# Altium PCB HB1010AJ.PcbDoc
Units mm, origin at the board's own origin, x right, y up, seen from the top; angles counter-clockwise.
Board outline 79 x 52 mm, 2 copper layers (Top Layer, Bottom Layer); 42 components, 44 nets, 138 pads, 30 vias.
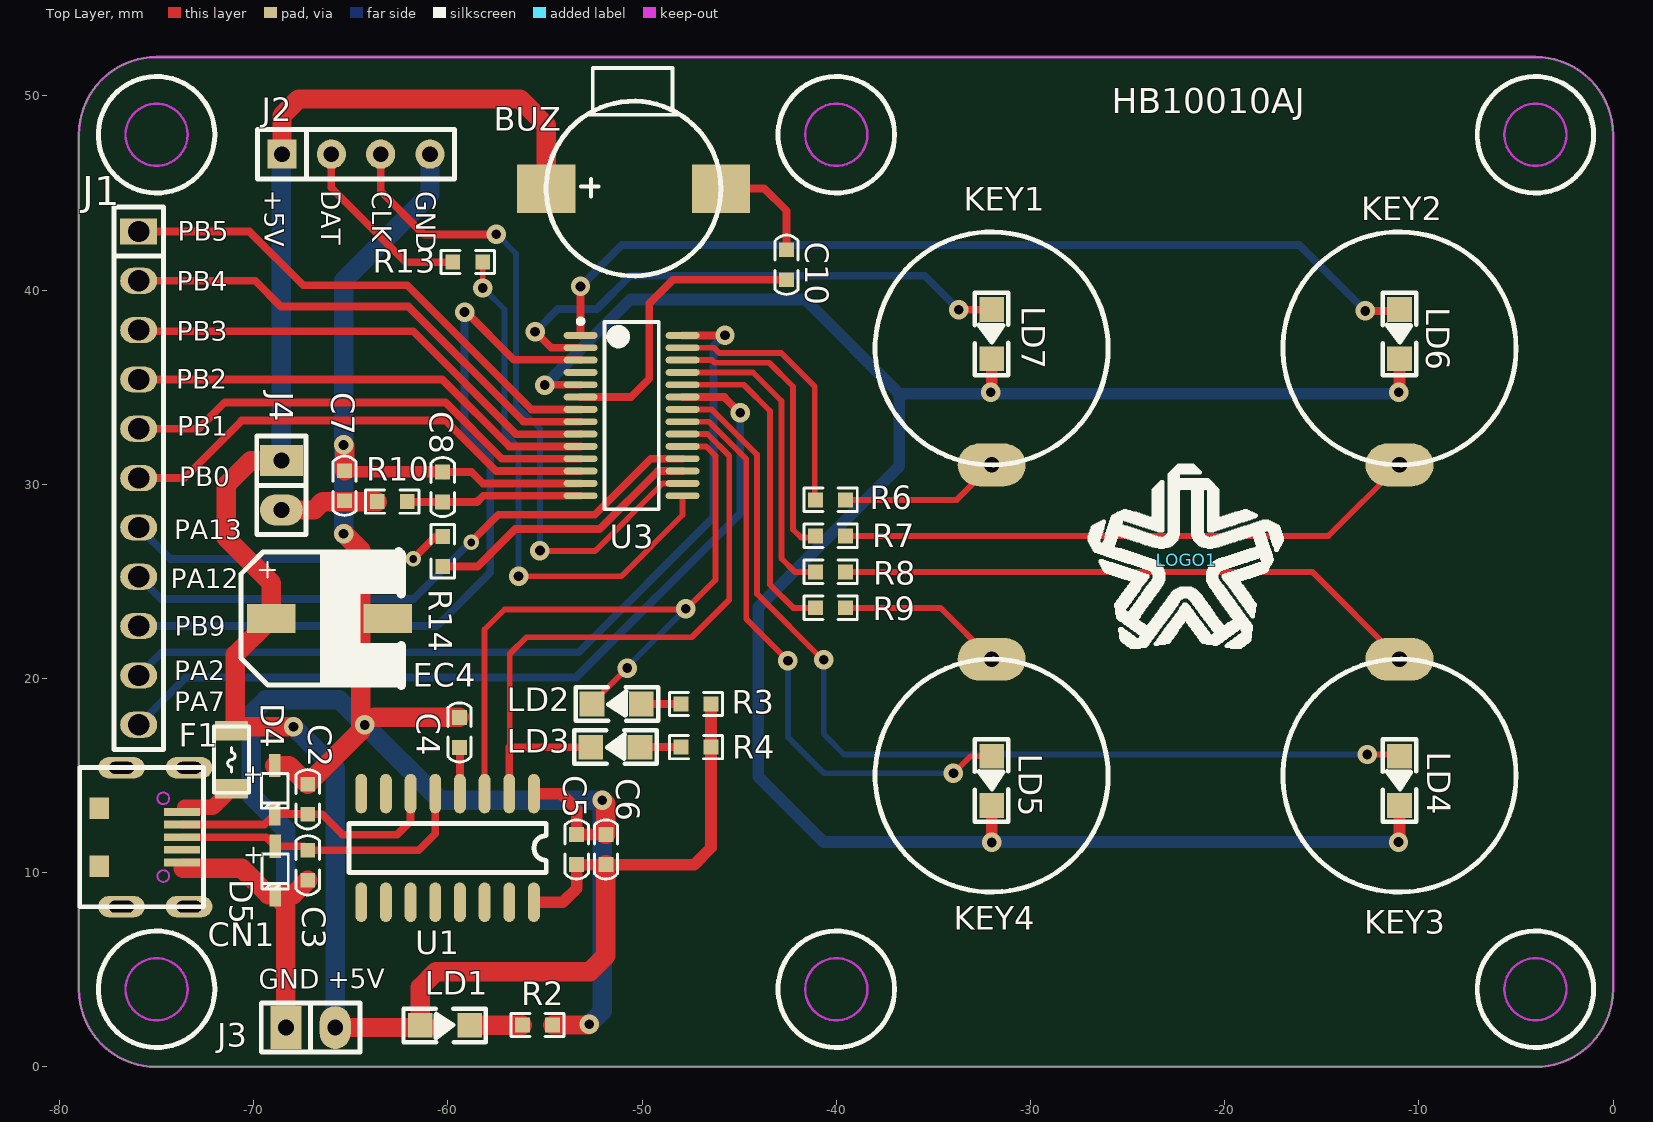
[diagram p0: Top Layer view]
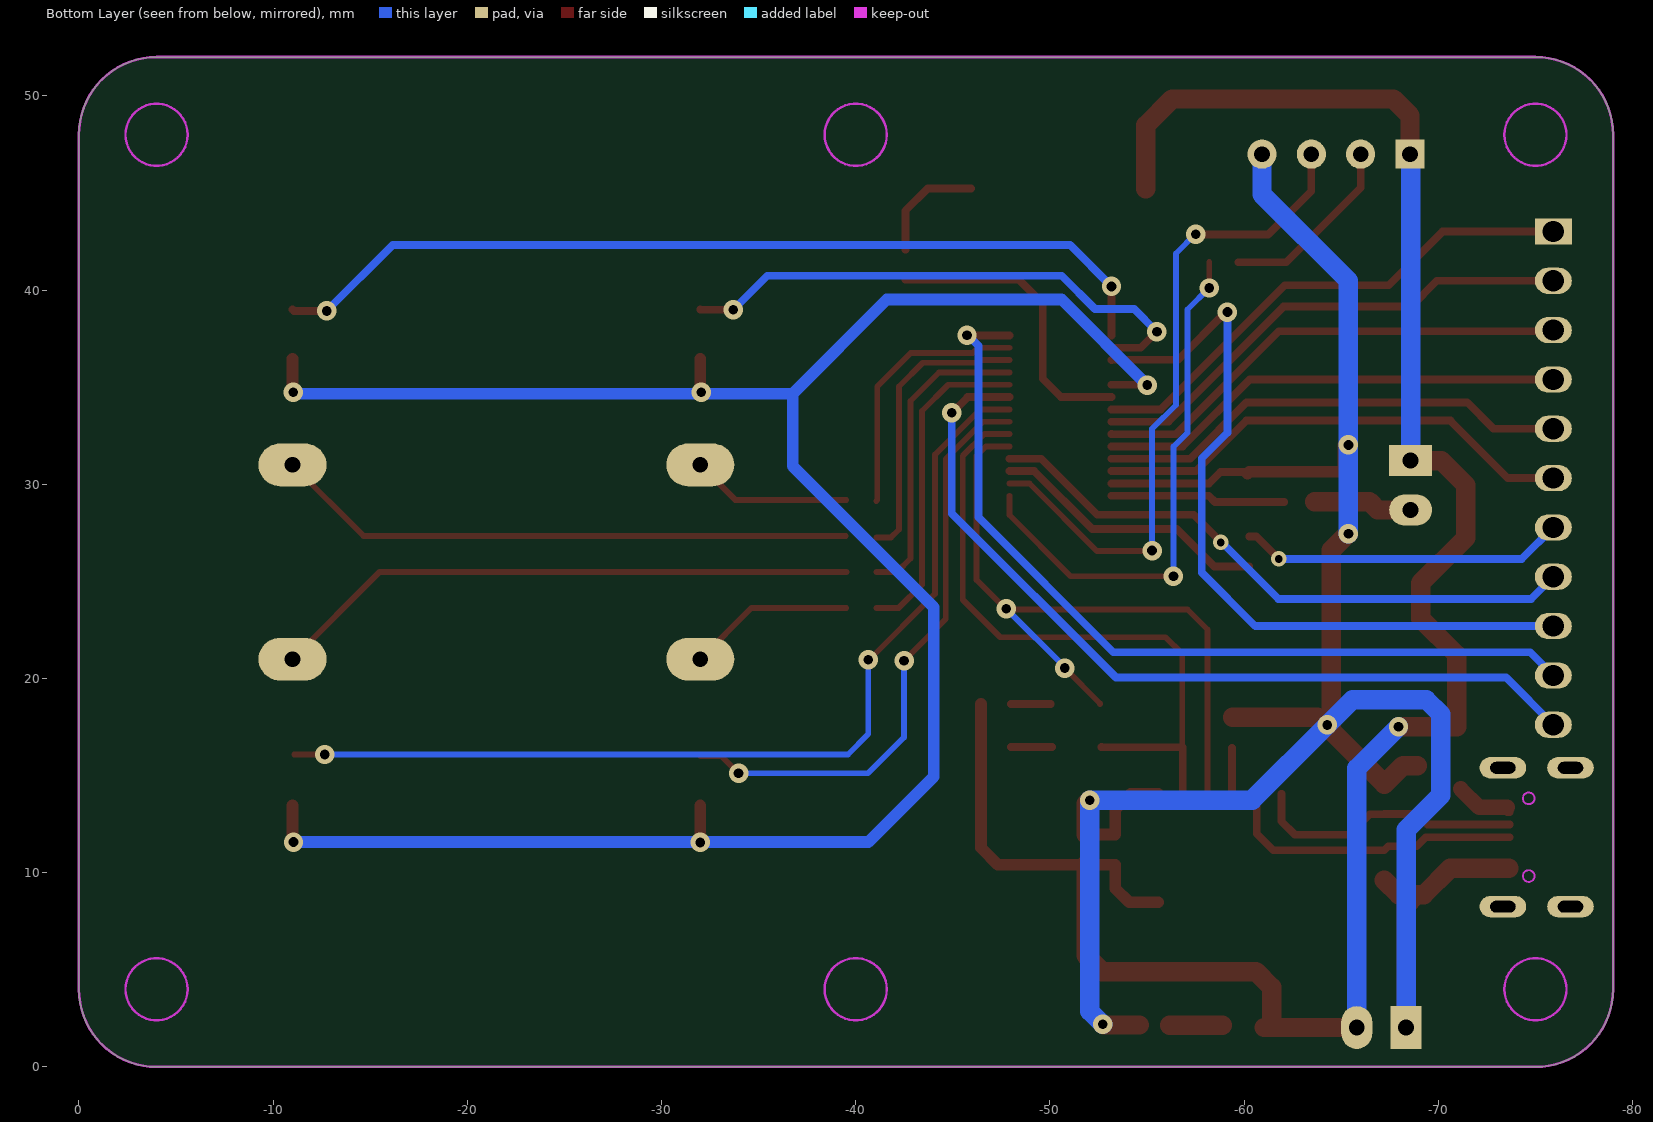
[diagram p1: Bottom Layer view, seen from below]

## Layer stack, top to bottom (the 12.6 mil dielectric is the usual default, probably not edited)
Top Layer: signal copper 0.0356
Dielectric: dielectric 0.32, FR-4, Dk 4.8
Bottom Layer: signal copper 0.0356

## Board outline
-79,4 -79,48 cw(c-75,48) -75,52 -4,52 cw(c-4,48) 0,48 0,4 cw(c-4,4) -4,0 -75,0 cw(c-75,4)

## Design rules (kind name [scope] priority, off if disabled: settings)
Clearance 板边 [All] p1 off: gap=0.6
Clearance [All] p2: gap=0.2
ComponentClearance [All] p1 off: gap=0.254 collisioncheckmode=3 verticalgap=0.254 showdistances=FALSE
MinimumSolderMaskSliver [All] p1: minsoldermaskwidth=0
PlaneClearance [All] p1: clearance=0.6
PlaneConnect [All] p1: planeconnectstyle=Relief reliefexpansion=0.508 reliefentries=4 reliefconductorwidth=0.254 reliefairgap=0
PolygonConnect PolygonConnect_1 [IsVia] p1: connectstyle=Direct reliefconductorwidth=0.254 reliefentries=4 polygonreliefangle="90 Angle"
PolygonConnect [All] p2: connectstyle=Relief reliefconductorwidth=0.3 reliefentries=4 polygonreliefangle="90 Angle"
RoutingVias [All] p1: holewidth=0.5 width=1 viastyle="Through Hole" minholewidth=0.4 minwidth=0.8 maxholewidth=0.6 maxwidth=1.2
SilkToSilkClearance [All] p1: silktosilkclearance=0
SilkscreenOverComponentPads SilkToSolderMaskClearance [IsPad] p1: minsilkscreentomaskgap=0
SolderMaskExpansion [All] p1: expansion=0.102
TestPointUsage FabricationTestPointUsage [All] p1: valid=0 allowmultiple=FALSE
Testpoint FabricationTestpoint [All] p1: side=3 testpointundercomponent=TRUE minsize=1.016 maxsize=2.54 preferedsize=1.524 minholesize=0 maxholesize=1.016 preferedholesize=0.813 testpointgrid=0.025 style=297 order=0-112345678
Width [All] p1: maxlimit=1 minlimit=0.3 preferedwidth=0.3
18 further rules are at their usual default settings.

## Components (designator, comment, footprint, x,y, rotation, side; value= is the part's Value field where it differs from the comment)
BUZ "BUZZ" BUZZ-90X32-SMD -50.44,45.23 r0 top
C2 "DNP/100pF/50V" 0603C -67.22,14.56 r270 top
C3 "DNP/100pF/50V" 0603C -67.22,11.16 r270 top
C4 "0.1uF/25V" 0603C -59.4,18 r270 top
C5 "10uF/25V" 0603C -53.37,11.97 r270 top
C6 "0.1uF/25V" 0603C -51.86,11.97 r270 top
C7 "10uF/25V" 0603C -65.32,29.15 r90 top
C8 "0.1uF/25V" 0603C -60.27,29.09 r90 top
C10 "0603-25V-2.2μF±10% X5R" 0603c -42.56,40.53 r90 top
CN1 "USB micro 5P" "MicroUSB - 7P2" -73.68,11.83 r270 top
D4 "DNP/PESD3V3L1BA" SOD-323 -68.9,15.62 r270 top
D5 "DNP/PESD3V3L1BA" SOD-323 -68.88,11.47 r270 top
EC4 "220uF±20% 10V SMD,6.3x5.4mm" ECAP-D6.3 -66.09,23.09 r0 top
F1 "6V 500mA" SF1206 -71.15,15.82 r90 top
J1 "CON11" sip11 -75.92,43.02 r270 top
J2 "CON4" SIP4 -68.54,47 r0 top
J3 "" sip2 -68.34,2.03 r0 top
J4 "" SIP2 -68.57,31.22 r270 top
KEY1 "" 弹簧6MM -32,37 r0 top locked
KEY2 "" 弹簧6MM -11,37 r0 top locked
KEY3 "" 弹簧6MM -11,15 r180 top locked
KEY4 "" 弹簧6MM -32,15 r180 top locked
LD1 "17-21SURC/S530-A3/TR8  发光二极管/0805 红灯 (Iv=61mcd(Typ) @IF=20mA)" D0805 -61.42,2.14 r0 top
LD2 "DNP" D0805 -50.04,18.69 r180 top
LD3 "DNP" D0805 -50.11,16.47 r180 top
LD4 "17-21SURC/S530-A3/TR8  发光二极管/0805 红灯 (Iv=61mcd(Typ) @IF=20mA)" D0805 -11,16 r270 top
LD5 "17-21SURC/S530-A3/TR8  发光二极管/0805 红灯 (Iv=61mcd(Typ) @IF=20mA)" D0805 -32,16 r270 top
LD6 "17-21SURC/S530-A3/TR8  发光二极管/0805 红灯 (Iv=61mcd(Typ) @IF=20mA)" D0805 -11,39 r270 top
LD7 "17-21SURC/S530-A3/TR8  发光二极管/0805 红灯 (Iv=61mcd(Typ) @IF=20mA)" D0805 -32,39 r270 top
LOGO1 "LOGO" LOGO_HED_10mm -21.96,26.1 r0 top
R2 "1K" 0603 -56.16,2.16 r0 top
R3 "DNP" 0603 -46.45,18.69 r180 top
R4 "DNP" 0603 -46.45,16.47 r180 top
R6 "10KΩ(1002) ±1% 0603WAF1002T5E" 0603 -39.52,29.2 r180 top
R7 "10KΩ(1002) ±1% 0603WAF1002T5E" 0603 -39.52,27.347 r180 top
R8 "10KΩ(1002) ±1% 0603WAF1002T5E" 0603 -39.52,25.493 r180 top
R9 "10KΩ(1002) ±1% 0603WAF1002T5E" 0603 -39.52,23.64 r180 top
R10 "0603WAF0000T5E 0R 1% 0603" R0603 -63.64,29.11 r0 top
R13 "0603WAF0000T5E 0R 1% 0603" R0603 -59.75,41.45 r0 top
R14 "0603WAF0000T5E 0R 1% 0603" R0603 -60.26,27.32 r270 top
U1 "CH340C  SOP-16_150mil" SO-16 -55.57,14.07 r270 top
U3 "CIU32F011I3FBxJ" SSOP28 -50.54,33.54 r0 top

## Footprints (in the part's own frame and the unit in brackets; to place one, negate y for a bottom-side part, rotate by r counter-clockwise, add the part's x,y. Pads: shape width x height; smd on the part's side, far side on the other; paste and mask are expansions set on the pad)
0603 [mil]
  rect 30x30 smd: 1(0,0) 2(61.02,0)
  silkscreen extent -24,-24 85,24
0603C [mil]
  rect 30x30 smd: 1(0,0) 2(61.02,0)
  silkscreen extent -29,-24 90,24
0603c [mil]
  rect 30x30 smd: 1(0,0) 2(61.02,0)
  silkscreen extent -29,-24 90,24
BUZZ-90X32-SMD [mm]
  rect 3x2.5 smd: 1(-4.5,0) 2(4.5,0)
  silkscreen extent -4.5,-4.5 4.5,6.2
D0805 [mm]
  rect 1.27x1.27 smd: 1(0,0) 2(2.54,0)
  silkscreen extent -0.86,-0.86 3.38,0.86
ECAP-D6.3 [mm]
  rect 2.5x1.5 smd: 1(-3,-0.007) 2(3,-0.007)
  silkscreen extent -4.57,-3.43 3.68,3.43
LOGO_HED_10mm [mm]
  silkscreen extent -5,-4.47 4.9,4.88
"MicroUSB - 7P2" [mm] "MicroUSB"
  rect 0.4x1.85 smd: 1(-1.3,0) 2(-0.65,0) 3(0,0) 4(0.65,0) 5(1.3,0)
  oval 1.1x2.4 hole 0.6 slot 1.3 at 90 deg: 6(-3.575,0.355) 6(-3.575,-3.125) 6(3.575,0.355) 6(3.575,-3.125)
  rect 1.1x1 smd: 7(-1.5,-4.275) 7(1.5,-4.275)
  Keep-Out Layer circle w0.1: c-2,-0.975 r0.3
  Keep-Out Layer circle w0.1: c2,-0.975 r0.3
  silkscreen extent -3.58,-5.28 3.58,1.09
R0603 [mil]
  rect 30x30 smd: 1(0,0) 2(61.02,0)
  silkscreen extent -24,-24 85,24
SF1206 [mm]
  rrect10% 1x1.7 smd: 1(-1.5,0) 2(1.5,0)
  silkscreen extent -1.7,-0.9 1.7,0.9
sip2 [mm]
  rect 1.6x2.2 hole 0.813: 1(0,0)
  oval 1.6x2.2 hole 0.813: 2(2.54,0)
  silkscreen extent -1.27,-1.27 3.81,1.27
SIP2 [mm]
  rect 1.6x2.2 hole 0.813: 1(0,0)
  oval 1.6x2.2 hole 0.813: 2(2.54,0)
  silkscreen extent -1.27,-1.27 3.81,1.27
SIP4 [mm]
  rect 1.5x1.5 hole 0.813: 1(0,0)
  round 1.5 hole 0.813: 2(2.54,0) 3(5.08,0) 4(7.62,0)
  silkscreen extent -1.27,-1.27 8.89,1.27
sip11 [mil]
  rect 53x75 hole 43: 1(0,0)
  oval 53x75 hole 43: 2(100,0) 3(200,0) 4(300,0) 5(400,0) 6(500,0) 7(600,0) 8(700,0) 9(800,0) 10(900,0) 11(1000,0)
  silkscreen extent -50,-50 1050,50
SO-16 [mil]
  oval 80x24 smd: 1(0,0) 2(0,-50) 3(0,-100) 4(0,-150) 5(0,-200) 6(0,-250) 7(0,-300) 8(0,-350) 9(220,-350) 10(220,-300) 11(220,-250) 12(220,-200) 13(220,-150) 14(220,-100) 15(220,-50) 16(220,0)
  silkscreen extent 60,-375 160,25
SOD-323 [mm]
  rect 1.2x0.6 smd: 1(0.1,-0.007) 2(2.6,-0.007)
  silkscreen extent 0.5,-0.69 2.3,0.66
SSOP28 [mm]
  oval 1.75x0.35 smd: 1(-2.625,4.127) 2(-2.625,3.492) 3(-2.625,2.857) 4(-2.625,2.222) 5(-2.625,1.587) 6(-2.625,0.953) 7(-2.625,0.318) 8(-2.625,-0.318) 9(-2.625,-0.953) 10(-2.625,-1.587) 11(-2.625,-2.222) 12(-2.625,-2.857) 13(-2.625,-3.492) 14(-2.625,-4.127) 15(2.625,-4.127) 16(2.625,-3.492) 17(2.625,-2.857) 18(2.625,-2.222) 19(2.625,-1.587) 20(2.625,-0.953) 21(2.625,-0.318) 22(2.625,0.318) 23(2.625,0.953) 24(2.625,1.587) 25(2.625,2.222) 26(2.625,2.857) 27(2.625,3.492) 28(2.625,4.127)
  silkscreen extent -2.75,-4.83 1.4,4.98, body extent -1.95,-4.95 1.95,4.95, height 1.75
弹簧6MM [mm]
  oval 3.5x2.2 hole 0.8: 1(0,-6)
  silkscreen extent -6,-6 6,6

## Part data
C2 C3 C4 C5 C6 C10: library part "cap 0603", "贴片电容"
C7 C8: library part CAP
D4 D5: library part TVS
EC4: library part E_CAP01
F1: library part Fuse_SMD, "贴片保险丝"
J1 J2: "Connector"
J3: library part CON2, "Connector"
J4: library part CON2, "2.54mm 1*2P?公插针/2.54mm 1*2P 直 排针"
KEY1 KEY2 KEY3 KEY4: library part CHUMO-PAD
LD1 LD2 LD3 LD4 LD5 LD6 LD7: library part LED
R2 R3 R4: library part "res 0603", "贴片电阻"
R6 R7 R8 R9: library part RES1
R10 R13 R14: library part Res2, "Resistor"
U1: library part CH340C, "IC"

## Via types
v1: diameter 1, hole 0.5, Top Layer to Bottom Layer, tented both sides, 28 vias
v2: diameter 0.8, hole 0.4, Top Layer to Bottom Layer, tented both sides, 2 vias

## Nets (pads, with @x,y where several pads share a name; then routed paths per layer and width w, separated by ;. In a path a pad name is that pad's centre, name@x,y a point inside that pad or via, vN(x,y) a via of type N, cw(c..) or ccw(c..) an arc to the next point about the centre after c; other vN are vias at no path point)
+5V: BUZ.1 C5.2 C6.2 EC4.1 F1.2 J2.1 J3.2 J4.1 LD1.1 R3.1 R4.1 U1.16 | length 112.5
  Top Layer w0.6: U1.16 -54.078,8.482 -53.37,9.19 C5.2 C6.2 -47.32,10.42 -46.45,11.29 R3.1
  Top Layer w1: J4.1 -70.15,31.22 -71.41,29.96 -71.41,27.24 -69.09,24.92 EC4.1 -70.95,21.223 -70.95,17.52 v1(-67.95,17.52) ; J2.1 -68.54,48.99 -67.69,49.84 -56.29,49.84 -54.94,48.49 BUZ.1 ; J3.2 LD1.1@-61.03,2.03 ; LD1.1 -61.42,4.1 -60.61,4.91 -52.69,4.91 -51.86,5.74 C6.2
  Bottom Layer w1: J4.1 -68.57,46.97 J2.1 ; v1(-67.95,17.52) -65.8,15.37 J3.2
BUZ: C10.1 U3.6 | length 15.4
  Top Layer w0.4: U3.6 -50.578,34.492 -49.63,35.44 -49.63,39.31 -48.41,40.53 C10.1
CLK: J2.3 U3.16 | length 34.8
  Top Layer w0.3: v1@-55.24,26.56 -52.43,26.56 -48.95,30.04 -47.923,30.04 U3.16
  Top Layer w0.4: J2.3 -63.46,45.09 -61.23,42.86 v1@-57.51,42.86
  Bottom Layer w0.3: v1@-57.51,42.91 -56.49,41.89 -56.49,34.09 -55.26,32.86 v1(-55.26,26.59)
  other v1: -57.51,42.87
COM1: LD4.2 LD5.2 LD6.2 LD7.2 U3.5 | length 114.1
  Top Layer w0.4: v1@-55.037,35.127 U3.5
  Top Layer w0.6: v1(-32.04,34.74) -32,34.78 LD7.2 ; v1(-32,11.56) LD5.2 ; v1(-11.05,11.58) -11,11.63 LD4.2 ; v1(-11.04,34.74) -11,34.78 LD6.2
  Bottom Layer w0.6: v1(-55.01,35.11) -50.6,39.52 -41.6,39.52 -36.75,34.67 ; v1(-11.05,11.58) -40.65,11.58 -44.02,14.95 -44.02,23.67 -36.75,30.94 -36.75,34.67 ; v1(-11.04,34.74) -11.11,34.67 -36.75,34.67
D_N: C2.2 CN1.2 D4.2 U1.6 | length 14.1
  Top Layer w0.4: CN1.2 -69.447,12.48 D4.2 C2.2@-67.23,13.02 ; C2.2 -66.47,13.01 -65.42,11.96 -62.62,11.96 -61.92,12.66 U1.6
D_P: C3.1 CN1.3 D5.1 U1.5 | length 15.7
  Top Layer w0.4: CN1.3 -69.347,11.83 D5.1 -67.43,11.37 C3.1 -61.5,11.16 -60.65,12.01 U1.5
DAT: J2.2 R13.1 | length 9.6
  Top Layer w0.4: J2.2 -66,45.27 -62.16,41.43 R13.1@-59.71,41.43
GND: C2.1 C3.2 C4.1 C5.1 C6.1 C7.2 C8.2 CN1.5 D4.1 D5.2 EC4.2 J2.4 J3.1 R2.2 U1.1 U3.13 | length 128.5
  Top Layer w0.4: C8.2 -58.79,30.64 -58.197,30.047 U3.13
  Top Layer w0.6: C7.2@-65.26,30.64 C8.2 C8.2@-60.17,30.54 ; U1.1 -54.17,14.07 -53.37,13.27 C5.1 C6.1
  Top Layer w1: -73.64,10.24 -70.62,10.24 -69.25,8.87 D5.2 ; D4.1 -68.18,15.52 C2.1 v1@-64.49,17.29 ; J3.1 -68.34,8.323 D5.2 ; C3.2 -67.96,8.87 D5.2 ; v1(-65.37,27.45) -65.32,27.45 -64.49,26.62 v1@-64.49,17.61 ; v1(-65.37,32.03) -65.32,31.98 C7.2 ; -63.78,18 C4.1 ; R2.2 -52.76,2.16 v1(-52.72,2.2) ; v1(-52.05,13.74) -51.86,13.55 C6.1
  Bottom Layer w1: J3.1 -68.34,12.21 -70.13,14 -70.13,18.16 -69.38,18.91 -65.58,18.91 v1(-64.28,17.61) -60.41,13.74 v1(-52.05,13.74) -52.05,2.87 v1(-52.72,2.2) ; v1(-65.37,27.45) v1(-65.37,32.03) -65.37,40.48 -60.92,44.93 J2.4
LED1: LD6.1 U3.1 | length 47
  Top Layer w0.4: U3.1 v1@-53.165,40.2 ; v1(-12.77,38.93) -11.07,38.93 LD6.1
  Bottom Layer w0.4: v1(-53.17,40.19) -51.04,42.32 -16.16,42.32 v1(-12.77,38.93)
LED2: LD7.1 U3.2 | length 28.1
  Top Layer w0.4: v1(-55.51,37.86) -54.682,37.032 U3.2 ; v1(-33.69,38.99) -32.01,38.99 LD7.1
  Bottom Layer w0.4: v1(-55.51,37.86) -54.34,39.03 -52.32,39.03 -50.61,40.74 -35.44,40.74 v1(-33.69,38.99)
LED3: LD5.1 U3.21 | length 30.9
  Top Layer w0.3: U3.21 -46.558,33.222 -44.64,31.304 -44.64,23.07 v1(-42.49,20.92) ; v1(-33.97,15.12) -33.09,16 LD5.1
  Bottom Layer w0.3: v1(-42.49,20.92) -42.48,20.91 -42.48,16.97 -40.63,15.12 v1(-33.97,15.12)
LED4: LD4.1 U3.22 | length 50.6
  Top Layer w0.3: U3.22 -46.409,33.857 -44.08,31.529 -44.08,24.36 -40.68,20.96 v1(-40.65,20.96) ; v1(-12.66,16.09) LD4.1@-11.09,16.09
  Bottom Layer w0.3: v1(-40.65,20.96) -40.65,17.14 -39.6,16.09 v1(-12.66,16.09)
NetBUZ_2: BUZ.2 C10.2 | length 5.9
  Top Layer w0.4: BUZ.2 -43.71,45.23 -42.56,44.08 C10.2
NetC4_2: C4.2 U1.4 | length 2.4
  Top Layer w0.4: U1.4 C4.2@-59.38,16.43
NetC7_1: C7.1 J4.2 R10.1 | length 5.1
  Top Layer w1: J4.2 -66.88,28.68 -66.45,29.11 R10.1
NetC8_1: C8.1 R10.2 U3.14 | length 9
  Top Layer w0.4: R10.2@-62.07,29.09 C8.1 -58.5,29.09 -58.178,29.412 U3.14
NetKEY1_1: KEY1.1 R6.1 | length 8.3
  Top Layer w0.3: R6.1@-39.51,29.2 -33.8,29.2 KEY1.1
NetKEY2_1: KEY2.1 R7.1 | length 30
  Top Layer w0.3: R7.1@-39.49,27.347 -14.653,27.347 KEY2.1
NetKEY3_1: KEY3.1 R8.1 | length 30.4
  Top Layer w0.3: R8.1@-39.53,25.493 -15.493,25.493 KEY3.1
NetKEY4_1: KEY4.1 R9.1 | length 8.6
  Top Layer w0.3: R9.1@-39.51,23.64 -34.64,23.64 KEY4.1
NetLD1_2: LD1.2 R2.1 | length 2.7
  Top Layer w1: LD1.2 R2.1@-56.18,2.14
NetLD2_1: LD2.1 R3.2 | length 2
  Top Layer w0.4: LD2.1 R3.2
NetLD3_1: LD3.1 R4.2 | length 2.1
  Top Layer w0.4: LD3.1 R4.2
NetR13_2: R13.2 U3.15 | length 27.7
  Top Layer w0.3: v1(-58.21,40.11) -58.2,40.12 R13.2 ; v1@-56.35,25.27 -51.06,25.27 -47.915,28.415 U3.15
  Bottom Layer w0.3: v1@-58.2,40.12 -57.08,39 -57.08,32.66 -56.36,31.94 v1(-56.36,25.27)
NetR14_2: R14.2 U3.17 | length 14.4
  Top Layer w0.4: R14.2 -58.46,25.77 -56.53,27.7 -52.18,27.7 -49.198,30.682 U3.17
PA2: J1.10 U3.28 | length 44.8
  Top Layer w0.4: U3.28 v1@-45.733,37.667
  Bottom Layer w0.4: J1.10 -74.73,21.35 -53.27,21.35 -46.32,28.3 -46.32,37.13 v1@-45.71,37.74
  other v1: -45.73,37.67
PA7: J1.11 U3.23 | length 44
  Top Layer w0.4: U3.23 -45.762,34.492 v1@-44.92,33.65
  Bottom Layer w0.4: J1.11 -73.49,20.05 -53.4,20.05 -44.95,28.5 v1(-44.95,33.68)
PA12: J1.8 U3.18 | length 31.5
  Top Layer w0.4: v2@-58.815,27.025 -57.41,28.43 -52.44,28.43 -49.553,31.317 U3.18
  Bottom Layer w0.4: J1.8 -74.78,24.1 -61.76,24.1 -58.85,27.01 v2(-58.8,27.01)
PA13: J1.7 R14.1 | length 16.8
  Top Layer w0.4: v2(-61.78,26.16) -60.62,27.32 R14.1
  Bottom Layer w0.4: J1.7 -74.3,26.16 v2(-61.78,26.16)
PB0: J1.6 U3.12 | length 25.1
  Top Layer w0.4: J1.6 -73.58,30.32 -70.62,33.28 -60.11,33.28 -57.512,30.682 U3.12
PB1: J1.5 U3.11 | length 24.5
  Top Layer w0.4: J1.5 -72.84,32.86 -71.48,34.22 -60.12,34.22 -57.22,31.32 -53.168,31.32 U3.11
PB2: J1.4 U3.10 | length 24.2
  Top Layer w0.4: J1.4 -61.03,35.4 ; -61.02,35.39 -61.03,35.4 ; U3.10 -56.842,31.952 -60.29,35.4 -61.03,35.4
PB3: J1.3 U3.9 | length 25
  Top Layer w0.4: J1.3 -75.86,37.88 -61.79,37.88 -56.49,32.58 -53.172,32.58 U3.9
PB4: J1.2 U3.8 | length 25.8
  Top Layer w0.4: J1.2 -69.92,40.48 -68.59,39.15 -62.03,39.15 -56.1,33.22 -53.168,33.22 U3.8
PB5: J1.1 U3.7 | length 26.6
  Top Layer w0.4: J1.1 -70.22,43.02 -67.45,40.25 -62.1,40.25 -55.708,33.857 U3.7
PB8: U3.4
PB9: J1.9 U3.3 | length 40.2
  Top Layer w0.4: v1(-59.14,38.87) -59.06,38.87 -56.61,36.42 -53.188,36.42 U3.3
  Bottom Layer w0.4: J1.9 -60.58,22.7 -57.82,25.46 -57.82,31.34 -59.14,32.66 v1(-59.14,38.87)
TK1: R6.2 U3.27 | length 13.6
  Top Layer w0.3: U3.27 -46.295,37.032 -46.025,36.762 -42.832,36.762 -41.11,35.04 -41.11,29.19 R6.2@-41.06,29.14
TK2: R7.2 U3.26 | length 14.9
  Top Layer w0.3: U3.26 -46.407,36.397 -46.272,36.262 -43.452,36.262 -42.23,35.04 -42.23,27.68 -41.81,27.26 R7.2@-41.07,27.26
TK3: R8.2 U3.25 | length 15.8
  Top Layer w0.3: U3.25 -44.292,35.762 -42.82,34.29 -42.82,26.18 -42.133,25.493 R8.2
TK4: R9.2 U3.24 | length 16.8
  Top Layer w0.3: U3.24 -44.767,35.127 -43.41,33.77 -43.41,24.83 -42.22,23.64 R9.2
UAR1_RX: LD3.2 U1.2 U3.20 | length 34.1
  Top Layer w0.3: -56.84,16.46 -56.81,16.49 -56.81,21.27 -55.95,22.13 -47.44,22.13 -45.51,24.06 -45.51,31.467 -46.63,32.587 U3.20
  Top Layer w0.4: U1.2 -56.84,16.46 -52.66,16.46 LD3.2
UAR1_TX: LD2.2 U1.3 U3.19 | length 36.7
  Top Layer w0.3: U1.3 -58.11,22.52 -57.08,23.55 -47.75,23.55 -46.22,25.08 -46.22,31.47 -46.702,31.952 U3.19 ; LD2.2 -52.58,18.72 v1(-50.76,20.54)
  Bottom Layer w0.3: v1@-50.85,20.5 v1(-47.75,23.6)
VBUS: CN1.1 F1.1 | length 2.9
  Top Layer w0.4: CN1.1 CN1.1@-73.55,13.13
  Top Layer w0.8: -73.55,13.37 -72.1,13.37 F1.1
pads on no net: CN1.4 CN1.6 CN1.7 U1.7 U1.8 U1.9 U1.10 U1.11 U1.12 U1.13 U1.14 U1.15

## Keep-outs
Keep-Out Layer:
  circle w0.127: c-75,4 r1.6
  circle w0.127: c-40,4 r1.6
  circle w0.127: c-4,4 r1.6
  circle w0.127: c-4,48 r1.6
  circle w0.127: c-75,48 r1.6
  circle w0.127: c-40,48 r1.6
  lines w0.127: -75,52.01 -4,52.01 ; 0,4 cw(c-4,4) -4,0 -75,0 cw(c-75,4) -79,4 -79,48 cw(c-75,48) -75,52 -4,52 cw(c-4,48) 0,48 ; 0,4 0,48 ; 0,4 0,48

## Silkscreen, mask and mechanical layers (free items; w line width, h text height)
Top Overlay:
  circle w0.254: c-4,48 r3
  circle w0.254: c-4,4 r3
  circle w0.254: c-40,4 r3
  circle w0.254: c-40,48 r3
  circle w0.254: c-75,48 r3
  circle w0.254: c-75,4 r3
  text "HB10010AJ" at -25.82,49.12 h1.3
  text "+5V" at -69.42,45.16 h1 r270
  text "DAT" at -66.53,45.13 h1 r270
  text "CLK" at -63.89,45.1 h1 r270
  text "GND" at -61.64,45.08 h1 r270
  text "PB5" at -73.92,42.55 h1
  text "PB4" at -73.96,39.96 h1
  text "PB3" at -73.96,37.4 h1
  text "PB2" at -73.98,34.91 h1
  text "PB1" at -73.93,32.5 h1
  text "PB0" at -73.84,29.9 h1
  text "PA13" at -74.1,27.17 h1
  text "PA12" at -74.26,24.64 h1
  text "PB9" at -74.07,22.2 h1
  text "PA2" at -74.09,19.91 h1
  text "PA7" at -74.09,18.32 h1
  text "+5V" at -66.18,4.06 h1
  text "GND" at -69.75,4.03 h1
Mechanical 1:
  circle w0.127: c-40,4 r1.6
  circle w0.127: c-4,48 r1.6
  circle w0.127: c-4,4 r1.6
  circle w0.127: c-75,4 r1.6
  circle w0.127: c-75,48 r1.6
  circle w0.127: c-40,48 r1.6
  lines w0.127: -79,4 ccw(c-75,4) -75,0 -4,0 ccw(c-4,4) 0,4 0,48 ccw(c-4,48) -4,52 -75,52 ccw(c-75,48) -79,48 -79,4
